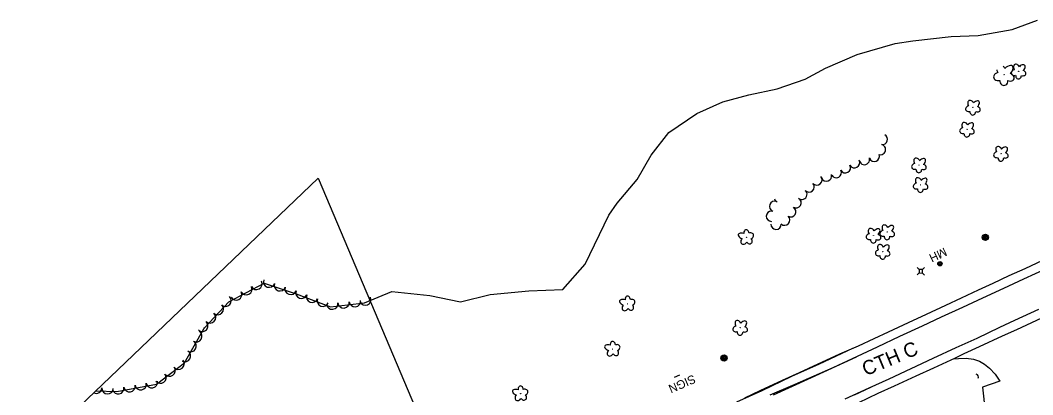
# Model space of a CAD drawing. Extents: x 588843 to 2552415, y 180129 to 269402.
# Drawn here: x 592527 to 593237, y 187898 to 188161 of the extents above; entities that cross this region are included whole.
import ezdxf

# ---------------------------------------------------------------- set-up
doc = ezdxf.new("R2010")
doc.units = 0
for name, color, linetype in [('Default', 7, 'Continuous'), ('E_DRN', 7, 'Continuous'), ('E_DWY', 7, 'Continuous'), ('E_LAND_TreeLine_P', 7, 'Continuous'), ('E_LAND_Vegetation', 7, 'Continuous'), ('E_MISCPROP', 7, 'Continuous'), ('E_RDWY', 7, 'Continuous'), ('E_RDWY_Gravel', 7, 'Continuous'), ('E_RDWY_Text', 7, 'Continuous'), ('E_SGN', 7, 'Continuous'), ('E_SGN_Text', 7, 'Continuous'), ('E_UTL_AG_Bold', 7, 'Continuous'), ('E_UTL_MH', 7, 'Continuous'), ('E_UTL_MH_Text', 7, 'Continuous'), ('Level 11', 7, 'Continuous'), ('Level 18', 7, 'Continuous')]:
    doc.layers.add(name, color=color, linetype=linetype)

# ---------------------------------------------------------------- blocks, each defined once
blk = doc.blocks.new('POLE')
at = {"layer": 'Default'}
for radius in [4.46, 3.35, 2.23, 1.12]:
    blk.add_circle((0, 0), radius, dxfattribs=at)
blk = doc.blocks.new('PED')
at = {"layer": 'Default'}
for p, q in [((-2.5, 2.5), (-5.3, 5.3)), ((2.5, 2.5), (5.3, 5.3)), ((-2.5, -2.5), (-5.3, -5.3)), ((2.5, -2.5), (5.3, -5.3))]:
    blk.add_line(p, q, dxfattribs=at)
blk.add_lwpolyline([(-2.5, -2.5), (2.5, -2.5), (2.5, 2.5), (-2.5, 2.5)], close=True, dxfattribs=at)
blk = doc.blocks.new('MHO')
at = {"layer": 'Default'}
for centre, radius in [((0.1, -0.1), 3), ((0.1, -0.1), 2.43), ((0.1, -0.1), 1.94), ((0, -0.2), 1.21)]:
    blk.add_circle(centre, radius, dxfattribs=at)
blk = doc.blocks.new('MHT')
at = {"layer": 'E_UTL_MH_Text'}
blk.add_text('MH', height=12, dxfattribs=at).set_placement((-9.8, -6))
blk = doc.blocks.new('DTRE')
at = {"layer": 'Default'}
blk.add_circle((-0.2, 0), 0.183, dxfattribs=at)
for centre, major_axis, ratio in [((-5.9, 0.2), (4.93, -0.12), 0.832022), ((-1.9, 5.3), (1.36, -4.98), 0.782863), ((4.1, 2.7), (-5.27, -2.93), 0.691916), ((-2.5, -5.2), (1.8, 4.86), 0.716896), ((3.5, -3.7), (-5.01, 4.58), 0.560249)]:
    blk.add_ellipse(centre, major_axis=major_axis, ratio=ratio, start_param=1.570796, end_param=4.712389, dxfattribs=at)
blk = doc.blocks.new('SIGN')
at = {"layer": 'Default'}
blk.add_text('SIGN', height=12, dxfattribs=at).set_placement((-18.5, -6))
blk = doc.blocks.new('CULV2')
at = {"layer": 'E_DRN'}
blk.add_arc((19.7, 14.8), 24.6, 216.8699, 323.1301, dxfattribs=at)

msp = doc.modelspace()

# ---------------------------------------------------------------- linework, layer by layer
at = {"layer": 'Default'}
msp.add_lwpolyline([(592409.33, 187552.38), (592387.7, 187602.85), (592346.9, 187678.64), (592735.79, 188050.05), (592838.09, 187808.48), (592884.47, 187677.08), (592985.3, 187391.41)], close=True, dxfattribs=at)
at = {"layer": 'E_DWY'}
msp.add_lwpolyline([(593181.14, 187923.46), (593184.66, 187923.83), (593189.86, 187923.9), (593194.99, 187923.27), (593199.32, 187921.93), (593202.92, 187919.84), (593206.32, 187917.03), (593210.26, 187912.74), (593213.53, 187907.85), (593201.33, 187903.65), (593203.21, 187886.64)], dxfattribs=at)
at = {"layer": 'E_LAND_TreeLine_P'}
for centre, start, end in [((593131.13, 188077.28), 264.22702, 60.57694), ((593129.86, 188070.11), 257.7698, 77.7698), ((593118.61, 188063.16), 197.58529, 17.58529), ((593125.53, 188065.41), 200.27615, 20.27615), ((593105.28, 188057.42), 208.46222, 28.46222), ((593111.69, 188060.9), 208.46222, 28.46222), ((593085.28, 188048.88), 222.20131, 42.20131), ((593092.01, 188051.53), 199.38787, 19.38787), ((593098.88, 188053.95), 208.46222, 28.46222), ((593079.88, 188043.98), 222.20131, 42.20131), ((593070.68, 188032.81), 239.54744, 59.54744), ((593074.78, 188038.8), 228.88949, 48.88949), ((593055.73, 188030.32), 70.0444, 250.0444), ((593059.05, 188036.8), 199.42708, 242.56742), ((593066.99, 188026.53), 239.54744, 59.54744), ((593053.46, 188023.43), 88.84101, 268.84101), ((593062.71, 188020.68), 227.54649, 47.54649), ((593056.69, 188017.84), 179.32642, 359.32642)]:
    msp.add_arc(centre, 3.64, start, end, dxfattribs=at)
at = {"layer": 'E_LAND_Vegetation'}
msp.add_circle((593216.51, 188122.49), 0.128, dxfattribs=at)
for centre, major_axis, ratio, start_param, end_param in [((593214.6, 188125.46), (2.04, -3.7), 0.691916, 1.570796, 2.099642), ((593219.11, 188125.09), (-3.22, -3.5), 0.560249, 1.570796, 4.712389), ((593212.78, 188121.32), (3.49, 0.94), 0.782863, 1.570796, 4.712389), ((593214.6, 188125.46), (2.04, -3.7), 0.691916, 4.214359, 4.712389), ((593220.17, 188120.86), (-3.4, 1.27), 0.716896, 1.570796, 4.712389), ((593216.39, 188118.51), (0.1, 3.45), 0.832022, 1.570796, 4.712389)]:
    msp.add_ellipse(centre, major_axis=major_axis, ratio=ratio, start_param=start_param, end_param=end_param, dxfattribs=at)
at = {"layer": 'E_RDWY'}
for points in [[(593246.47, 187986.83), (593230.06, 187979.31), (593216.02, 187972.81), (593201.4, 187966.08), (593187.42, 187959.53), (593172.4, 187952.64), (593159.13, 187946.46), (593143.24, 187939.07), (593127.49, 187931.68), (593113.53, 187925.18), (593096.4, 187917.32), (593069.83, 187905.59), (593052.38, 187898.15)], [(593240.77, 187958.15), (593223.85, 187950.37), (593213.35, 187945.49), (593197.33, 187937.84), (593182.68, 187931.16), (593166.48, 187923.69), (593151.12, 187916.54), (593135.63, 187909.31), (593121.8, 187902.99), (593104.99, 187895.16)]]:
    msp.add_lwpolyline(points, dxfattribs=at)
at = {"layer": 'E_RDWY_Gravel'}
for points in [[(593243.49, 187992.48), (593231.05, 187986.66), (593219.8, 187981.62), (593208.7, 187976.27), (593198.31, 187971.58), (593186.36, 187965.93), (593175.39, 187960.82), (593162, 187954.58), (593149.29, 187948.66), (593135.38, 187942.22), (593125.27, 187937.56), (593114.27, 187932.4), (593101.11, 187926.7), (593085.87, 187919.7), (593072.91, 187913.76), (593061.06, 187908.43), (593045.4, 187901.04), (593034.64, 187895.95)], [(593250.34, 187955.48), (593235.69, 187948.75), (593225.17, 187943.92), (593215.08, 187939.42), (593199, 187931.93), (593188.3, 187927), (593182.32, 187924.01), (593166.96, 187916.91), (593154.59, 187911.28), (593139.39, 187904.44), (593128.07, 187899.15), (593114.38, 187892.6)]]:
    msp.add_lwpolyline(points, dxfattribs=at)
at = {"layer": 'E_SGN'}
msp.add_lwpolyline([(592985.45, 187910.64), (592989.25, 187912.2)], dxfattribs=at)
at = {"layer": 'Level 11'}
for points in [[(593110.16, 187930.83), (593086.33, 187919.46), (593067.56, 187911.06), (593046.61, 187901.11), (593029.06, 187893.14)], [(593112.96, 187924.79), (593081.4, 187910.28), (593054.72, 187898.04)], [(593122.8, 187903.55), (593111.48, 187898.12)]]:
    msp.add_lwpolyline(points, dxfattribs=at)
at = {"layer": 'Level 18'}
for points in [[(592655.61, 187944.64), (592655.95, 187945.25), (592673.05, 187963.52), (592697.94, 187976.55), (592720.28, 187968.99), (592744.42, 187959.96), (592768.29, 187962.64), (592787.25, 187970.62), (592813.89, 187967.82), (592835.53, 187963.53), (592856.32, 187968.53), (592883.34, 187971.15), (592907.25, 187972.07), (592922.98, 187989.81), (592939.58, 188024.19), (592945.31, 188032.63), (592959.42, 188049.2), (592969.24, 188066.29), (592981.48, 188082.06), (593001.21, 188095.48), (593019.42, 188103.45), (593037.69, 188108.52), (593057.5, 188112.75), (593077, 188119.36), (593091.3, 188127.24), (593113.63, 188136.81), (593140.16, 188144.46), (593152.46, 188146.37), (593179.35, 188149.37), (593198.36, 188149.93), (593222.19, 188154.12), (593239.93, 188160.69)], [(592579.94, 187901.2), (592594.61, 187900.53), (592622.46, 187905.7), (592642.02, 187920.62), (592655.61, 187944.64)]]:
    msp.add_lwpolyline(points, dxfattribs=at)
for centre, start, end in [((592685.33, 187972.31), 207.63506, 27.61974), ((592692.41, 187976.01), 207.63506, 27.61974), ((592701.3, 187977.62), 161.31534, 341.30001), ((592708.87, 187975.06), 161.31534, 341.30001), ((592716.44, 187972.5), 161.31534, 341.30001), ((592670.82, 187964.2), 226.9105, 46.89518), ((592678.25, 187968.6), 207.63506, 27.61974), ((592724.03, 187969.82), 159.49664, 339.48132), ((592731.52, 187967.02), 159.49664, 339.48132), ((592739, 187964.22), 159.49664, 339.48132), ((592768.74, 187965.1), 202.84064, 22.82532), ((592665.37, 187958.37), 226.9105, 46.89518), ((592745.6, 187962.2), 186.41107, 6.39575), ((592753.54, 187963.09), 186.41107, 6.39575), ((592761.48, 187963.98), 186.41107, 6.39575), ((592659.91, 187952.54), 226.9105, 46.89518), ((592654.45, 187946.7), 226.9105, 328.96414), ((592654.45, 187946.7), 328.96414, 46.89518), ((592650.21, 187939.35), 240.50946, 60.49414), ((592646.28, 187932.4), 240.50946, 60.49414), ((592637.87, 187920.08), 217.34883, 37.33351), ((592642.35, 187925.45), 240.50946, 60.49414), ((592631.51, 187915.24), 217.34883, 37.33351), ((592625.16, 187910.39), 217.34883, 37.33351), ((592580.1, 187903.29), 244.06184, 357.38891), ((592588.09, 187902.92), 177.40424, 357.38891), ((592595.57, 187902.84), 190.50975, 10.49442), ((592603.42, 187904.3), 190.50975, 10.49442), ((592611.28, 187905.75), 190.50975, 10.49442), ((592619.14, 187907.21), 190.50975, 10.49442)]:
    msp.add_arc(centre, 4, start, end, dxfattribs=at)

# ---------------------------------------------------------------- block references
at = {"layer": 'E_DRN', "xscale": 0.0801265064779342, "yscale": 0.0801265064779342, "rotation": 113.55336994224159}
msp.add_blockref('CULV2', (593198.34, 187909.92), dxfattribs=at)
at = {"layer": 'E_LAND_Vegetation', "xscale": 0.5, "yscale": 0.5}
for p, rotation in [((593226.77, 188125.02), 89.80387544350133), ((593194.72, 188099.71), 89.80387544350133), ((593190.56, 188084.3), 89.80387544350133), ((593214.38, 188067.42), 89.80387544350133), ((593156.9, 188059.28), 89.80387544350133), ((593158.02, 188045.52), 89.80387544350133), ((593035.78, 188008.51), -156.56674682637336), ((593125.02, 188010.06), 89.80387544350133), ((593134.62, 188012.41), 89.80387544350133), ((593131.5, 187998.75), 89.80387544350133), ((592952.59, 187962), -156.56674682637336), ((593031.58, 187945.5), 89.80387544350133), ((592942.14, 187930.26), -156.56674682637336), ((592877.56, 187899.04), -156.56674682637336)]:
    msp.add_blockref('DTRE', p, dxfattribs=dict(at, rotation=rotation))
at = {"layer": 'E_MISCPROP', "xscale": 0.4999999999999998, "yscale": 0.4999999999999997, "rotation": 89.80387544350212}
for p in [(593203.41, 188008.67), (593020.21, 187924.08)]:
    msp.add_blockref('POLE', p, dxfattribs=at)
at = {"layer": 'E_SGN_Text', "xscale": 0.5, "yscale": 0.5, "rotation": -156.56674682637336}
msp.add_blockref('SIGN', (592991.36, 187906.17), dxfattribs=at)
at = {"layer": 'E_UTL_AG_Bold', "xscale": 0.4999999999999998, "yscale": 0.4999999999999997, "rotation": 89.80387544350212}
msp.add_blockref('PED', (593158.16, 187984.9), dxfattribs=at)
at = {"layer": 'E_UTL_MH', "xscale": 0.4999999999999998, "yscale": 0.4999999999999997, "rotation": 89.80387544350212}
msp.add_blockref('MHO', (593171.53, 187990.07), dxfattribs=at)
at = {"layer": 'E_UTL_MH_Text', "xscale": 0.4999999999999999, "yscale": 0.5, "rotation": -154.91840232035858}
msp.add_blockref('MHT', (593171.48, 187996.84), dxfattribs=at)

# ---------------------------------------------------------------- texts
at = {"layer": 'E_RDWY_Text'}
msp.add_text('CTH C', height=10, rotation=22.65006, dxfattribs=at).set_placement((593119.54, 187911.29))

doc.saveas('drawing.dxf')
